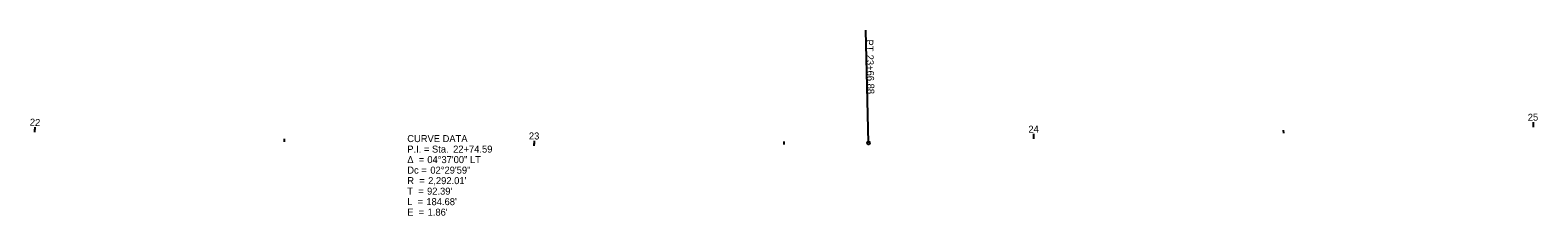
# Model space of a CAD drawing. Extents: x 2273904 to 2275373, y 654575 to 654883.
# Drawn here: x 2274704.3 to 2275006.1, y 654682.9 to 654719.9 of the extents above; entities that cross this region are included whole.
import ezdxf

# ---------------------------------------------------------------- set-up
doc = ezdxf.new("R2010")
doc.units = 0
for name, color, linetype in [('DR_P_Headwall', 7, 'Continuous'), ('DR_P_Storm_Sewer', 7, 'Continuous'), ('GE_X_Alignment_1000_Stations', 7, 'Continuous'), ('GE_X_Alignment_500_Stations', 7, 'Continuous'), ('PV_P_Drive', 7, 'Continuous'), ('PV_P_EOP', 7, 'Continuous')]:
    doc.layers.add(name, color=color, linetype=linetype)

msp = doc.modelspace()

# ---------------------------------------------------------------- linework, layer by layer
at = {"layer": 'DR_P_Storm_Sewer'}
for p, q in [((2274872.11, 654697.43), (2274871.58, 654719.93)), ((2274705.28, 654699.57), (2274705.31, 654700.17)), ((2275005.19, 654700.57), (2275005.17, 654701.57)), ((2274805.23, 654696.83), (2274805.24, 654697.43)), ((2274905.22, 654698.22), (2274905.21, 654698.82))]:
    msp.add_line(p, q, dxfattribs=at)
msp.add_circle((2274872.11, 654697.43), 0.3, dxfattribs=at)
at = {"layer": 'GE_X_Alignment_1000_Stations'}
for p, q in [((2274872.11, 654697.43), (2274871.58, 654719.93)), ((2274705.28, 654699.57), (2274705.33, 654700.57)), ((2274955.21, 654699.39), (2274955.19, 654699.99)), ((2275005.19, 654700.57), (2275005.17, 654701.57)), ((2274755.24, 654697.66), (2274755.26, 654698.26)), ((2274805.23, 654696.83), (2274805.24, 654697.83)), ((2274855.23, 654697.1), (2274855.22, 654697.7)), ((2274905.22, 654698.22), (2274905.2, 654699.22))]:
    msp.add_line(p, q, dxfattribs=at)
msp.add_circle((2274872.11, 654697.43), 0.3, dxfattribs=at)
at = {"layer": 'PV_P_Drive'}
for p, q in [((2274872.11, 654697.43), (2274871.58, 654719.93)), ((2275005.19, 654700.57), (2275005.18, 654701.17))]:
    msp.add_line(p, q, dxfattribs=at)
msp.add_circle((2274872.11, 654697.43), 0.3, dxfattribs=at)

# ---------------------------------------------------------------- texts
at = {"layer": 'DR_P_Headwall'}
for s, p in [('CURVE DATA', (2274779.81, 654697.58)), ('P.I. = Sta. ', (2274779.81, 654695.48)), ('22+74.59', (2274788.99, 654695.48)), ('Δ  = ', (2274779.81, 654693.38)), ('04°37\'00" LT', (2274783.82, 654693.38)), ('Dc = ', (2274779.81, 654691.28)), ('02°29\'59"', (2274784.43, 654691.28)), ('T  = ', (2274779.81, 654687.08)), ('R  = ', (2274779.81, 654689.18)), ("92.39'", (2274783.77, 654687.08)), ("2,292.01'", (2274783.99, 654689.18)), ('L  = ', (2274779.81, 654684.98)), ("184.68'", (2274783.63, 654684.98)), ('E  = ', (2274779.81, 654682.88)), ("1.86'", (2274783.88, 654682.88))]:
    msp.add_text(s, height=1.4, dxfattribs=at).set_placement(p)
at = {"layer": 'DR_P_Storm_Sewer'}
for s, rotation, p in [('PT', 271.351, (2274871.65, 654718.06)), ('23+66.88', 271.351, (2274871.72, 654715.02)), ('25', 1.351, (2275004.06, 654701.82))]:
    msp.add_text(s, height=1.4, rotation=rotation, dxfattribs=at).set_placement(p)
at = {"layer": 'GE_X_Alignment_1000_Stations'}
for s, rotation, p in [('PT', 271.351, (2274871.65, 654718.06)), ('23+66.88', 271.351, (2274871.72, 654715.02)), ('25', 1.351, (2275004.06, 654701.82)), ('22', 357.1793, (2274704.25, 654700.88)), ('24', 1.351, (2274904.12, 654699.44)), ('23', 359.6791, (2274804.15, 654698.11))]:
    msp.add_text(s, height=1.4, rotation=rotation, dxfattribs=at).set_placement(p)
at = {"layer": 'GE_X_Alignment_500_Stations'}
for s, p in [('CURVE DATA', (2274779.81, 654697.58)), ('P.I. = Sta. ', (2274779.81, 654695.48)), ('22+74.59', (2274788.99, 654695.48)), ('Δ  = ', (2274779.81, 654693.38)), ('04°37\'00" LT', (2274783.82, 654693.38)), ('Dc = ', (2274779.81, 654691.28)), ('02°29\'59"', (2274784.43, 654691.28)), ('T  = ', (2274779.81, 654687.08)), ('R  = ', (2274779.81, 654689.18)), ("92.39'", (2274783.77, 654687.08)), ("2,292.01'", (2274783.99, 654689.18)), ('L  = ', (2274779.81, 654684.98)), ("184.68'", (2274783.63, 654684.98)), ('E  = ', (2274779.81, 654682.88)), ("1.86'", (2274783.88, 654682.88))]:
    msp.add_text(s, height=1.4, dxfattribs=at).set_placement(p)
at = {"layer": 'PV_P_Drive'}
for s, p in [('PT', (2274871.65, 654718.06)), ('23+66.88', (2274871.72, 654715.02))]:
    msp.add_text(s, height=1.4, rotation=271.351, dxfattribs=at).set_placement(p)
at = {"layer": 'PV_P_EOP'}
for s, p in [('CURVE DATA', (2274779.81, 654697.58)), ('P.I. = Sta. ', (2274779.81, 654695.48)), ('22+74.59', (2274788.99, 654695.48)), ('Δ  = ', (2274779.81, 654693.38)), ('04°37\'00" LT', (2274783.82, 654693.38)), ('Dc = ', (2274779.81, 654691.28)), ('02°29\'59"', (2274784.43, 654691.28)), ('T  = ', (2274779.81, 654687.08)), ('R  = ', (2274779.81, 654689.18)), ("92.39'", (2274783.77, 654687.08)), ("2,292.01'", (2274783.99, 654689.18)), ('L  = ', (2274779.81, 654684.98)), ("184.68'", (2274783.63, 654684.98)), ('E  = ', (2274779.81, 654682.88)), ("1.86'", (2274783.88, 654682.88))]:
    msp.add_text(s, height=1.4, dxfattribs=at).set_placement(p)

doc.saveas('drawing.dxf')
